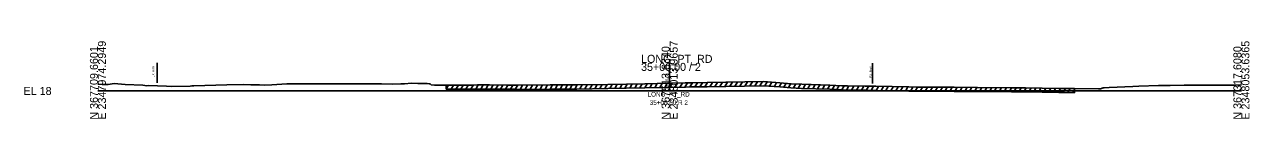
# Model space of a CAD drawing. Extents: x 974 to 2350744, y -10 to 368509.
# Drawn here: x 974.3 to 1402.8, y -9.7 to 17.3 of the extents above; entities that cross this region are included whole.
import ezdxf

# ---------------------------------------------------------------- set-up
doc = ezdxf.new("R2010")
doc.units = 0
for name, color, linetype in [('RD_GPK_XS_Cell', 7, 'Continuous'), ('RD_XS_ExGround', 7, 'Continuous'), ('RD_XS_ExPaveRet', 7, 'Continuous'), ('RD_XS_ExRW', 7, 'Continuous'), ('RD_XS_TX_Elev_EX', 7, 'Continuous'), ('RD_XS_TX_Station', 7, 'Continuous')]:
    doc.layers.add(name, color=color, linetype=linetype)

msp = doc.modelspace()

# ---------------------------------------------------------------- linework, layer by layer
at = {"layer": 'RD_GPK_XS_Cell'}
for p, q in [((1200, 0), (1200, 9.78)), ((1000, 0), (1200, 0)), ((1200, 0), (1400, 0))]:
    msp.add_line(p, q, dxfattribs=at)
at = {"layer": 'RD_XS_ExGround'}
msp.add_lwpolyline([(1000, 2.35), (1001.51, 2.29), (1003.53, 2.22), (1005.71, 2.57), (1009.54, 2.3), (1015.73, 1.98), (1017.13, 1.84), (1017.66, 1.87), (1024.01, 1.67), (1025.56, 1.59), (1032.29, 1.72), (1032.89, 1.78), (1033.59, 1.79), (1045.07, 2.19), (1050.94, 2.23), (1053.49, 2.08), (1056.56, 2.12), (1058.16, 2.01), (1060.88, 2.12), (1066.03, 2.48), (1071.83, 2.44), (1074.52, 2.45), (1079.84, 2.46), (1086.74, 2.43), (1089.22, 2.48), (1097.47, 2.51), (1099.16, 2.47), (1102.87, 2.42), (1105.96, 2.52), (1107.28, 2.5), (1109.68, 2.69), (1111.91, 2.65), (1115.17, 2.61), (1115.88, 2.5), (1116.19, 2.45), (1116.61, 2.09), (1117.72, 2.07), (1118.22, 2.07), (1118.95, 2.06), (1120.46, 2.04), (1121.67, 2.04), (1123.1, 2.04), (1124.36, 2.05), (1125.47, 2.05), (1128.44, 2.05), (1130.03, 2.06), (1131.45, 2.07), (1132.72, 2.08), (1133.84, 2.09), (1134.83, 2.1), (1136.93, 2.1), (1143.65, 2.04), (1145.62, 2.02), (1146.81, 1.99), (1158.24, 2.11), (1167.48, 2.11), (1178.38, 2.28), (1191.31, 2.5), (1200, 2.68), (1205.48, 2.79), (1207.41, 2.82), (1213.13, 2.91), (1232.79, 3.26), (1238.59, 2.81), (1242.49, 2.54), (1246.2, 2.34), (1256.07, 2.04), (1260.2, 1.81), (1262.23, 1.74), (1268.38, 1.68), (1272.18, 1.62), (1283.66, 1.38), (1286.85, 1.33), (1290.04, 1.35), (1299.49, 1.29), (1307.74, 1.26), (1319.56, 1.14), (1324.53, 1.1), (1336.17, 0.88), (1337.71, 0.86), (1341.62, 0.82), (1350.03, 0.76), (1350.76, 0.76), (1351.64, 1.1), (1351.95, 1.12), (1353.69, 1.23), (1362.03, 1.58), (1364.09, 1.65), (1371, 1.91), (1375.1, 1.96), (1380.04, 2), (1386.4, 2.04), (1397.63, 2), (1400, 2.15)], dxfattribs=at)
at = {"layer": 'RD_XS_ExPaveRet'}
for p, q in [((1121.87, 0.63), (1121.87, 2.07)), ((1121.87, 0.6), (1121.87, 2.04)), ((1121.87, 0.75), (1122.61, 2.04)), ((1123.52, 0.6), (1124.35, 2.05)), ((1125.25, 0.61), (1126.08, 2.05)), ((1126.98, 0.61), (1127.81, 2.05)), ((1128.72, 0.61), (1129.55, 2.05)), ((1130.45, 0.62), (1131.29, 2.06)), ((1132.19, 0.64), (1133.03, 2.08)), ((1133.94, 0.65), (1134.77, 2.1)), ((1135.68, 0.67), (1136.51, 2.1)), ((1137.41, 0.66), (1138.23, 2.09)), ((1139.13, 0.65), (1139.95, 2.07)), ((1140.85, 0.63), (1141.67, 2.06)), ((1142.57, 0.61), (1143.4, 2.04)), ((1144.29, 0.59), (1145.12, 2.02)), ((1146.01, 0.57), (1146.83, 1.99)), ((1147.74, 0.56), (1148.57, 2.01)), ((1149.48, 0.58), (1150.32, 2.03)), ((1151.22, 0.6), (1152.06, 2.04)), ((1152.97, 0.62), (1153.8, 2.06)), ((1154.71, 0.63), (1155.54, 2.08)), ((1156.45, 0.65), (1157.29, 2.1)), ((1158.19, 0.67), (1159.02, 2.11)), ((1159.93, 0.67), (1160.76, 2.11)), ((1161.66, 0.67), (1162.49, 2.11)), ((1163.39, 0.67), (1164.22, 2.11)), ((1165.12, 0.67), (1165.95, 2.11)), ((1166.86, 0.67), (1167.69, 2.11)), ((1168.6, 0.69), (1169.44, 2.14)), ((1170.35, 0.72), (1171.18, 2.17)), ((1172.09, 0.74), (1172.93, 2.19)), ((1173.84, 0.77), (1174.68, 2.22)), ((1175.59, 0.8), (1176.43, 2.25)), ((1177.34, 0.82), (1178.17, 2.27)), ((1179.08, 0.85), (1179.92, 2.3)), ((1180.83, 0.88), (1181.67, 2.33)), ((1182.58, 0.91), (1183.42, 2.37)), ((1184.33, 0.94), (1185.17, 2.4)), ((1186.08, 0.98), (1186.92, 2.43)), ((1187.83, 1.01), (1188.67, 2.46)), ((1189.58, 1.04), (1190.42, 2.49)), ((1191.33, 1.07), (1192.17, 2.52)), ((1193.09, 1.1), (1193.93, 2.56)), ((1194.84, 1.14), (1195.68, 2.59)), ((1196.59, 1.17), (1197.43, 2.63)), ((1198.34, 1.21), (1199.18, 2.66)), ((1200.1, 1.24), (1200.93, 2.7)), ((1201.85, 1.28), (1202.69, 2.73)), ((1203.6, 1.31), (1204.44, 2.77)), ((1205.35, 1.35), (1206.19, 2.8)), ((1207.1, 1.38), (1207.94, 2.83)), ((1208.85, 1.41), (1209.69, 2.86)), ((1210.6, 1.43), (1211.43, 2.88)), ((1212.34, 1.46), (1213.18, 2.91)), ((1214.09, 1.49), (1214.93, 2.94)), ((1215.84, 1.52), (1216.68, 2.97)), ((1217.59, 1.55), (1218.43, 3.01)), ((1219.34, 1.58), (1220.18, 3.04)), ((1221.09, 1.62), (1221.93, 3.07)), ((1222.84, 1.65), (1223.68, 3.1)), ((1224.59, 1.68), (1225.43, 3.13)), ((1226.34, 1.71), (1227.18, 3.16)), ((1228.09, 1.74), (1228.93, 3.19)), ((1229.84, 1.77), (1230.68, 3.22)), ((1231.59, 1.8), (1232.43, 3.25)), ((1233.31, 1.78), (1234.11, 3.16)), ((1234.97, 1.65), (1235.77, 3.03)), ((1236.63, 1.52), (1237.42, 2.9)), ((1238.29, 1.39), (1239.08, 2.78)), ((1239.95, 1.28), (1240.75, 2.66)), ((1241.62, 1.16), (1242.42, 2.55)), ((1243.29, 1.06), (1244.1, 2.46)), ((1244.97, 0.97), (1245.78, 2.37)), ((1246.66, 0.89), (1247.47, 2.31)), ((1248.36, 0.84), (1249.17, 2.25)), ((1250.06, 0.79), (1250.88, 2.2)), ((1251.76, 0.74), (1252.58, 2.15)), ((1253.46, 0.68), (1254.28, 2.1)), ((1255.17, 0.63), (1255.98, 2.04)), ((1256.86, 0.56), (1257.66, 1.95)), ((1258.53, 0.46), (1259.34, 1.85)), ((1260.21, 0.37), (1261.03, 1.78)), ((1261.91, 0.31), (1262.73, 1.73)), ((1263.63, 0.29), (1264.45, 1.72)), ((1265.35, 0.27), (1266.18, 1.7)), ((1267.07, 0.25), (1267.9, 1.68)), ((1268.79, 0.23), (1269.62, 1.66)), ((1270.51, 0.21), (1271.33, 1.63)), ((1272.23, 0.18), (1273.05, 1.6)), ((1273.94, 0.14), (1274.76, 1.56)), ((1275.65, 0.11), (1276.47, 1.53)), ((1277.36, 0.07), (1278.18, 1.49)), ((1279.07, 0.04), (1279.89, 1.46)), ((1280.79, 0), (1281.61, 1.43)), ((1282.5, -0.03), (1283.32, 1.39)), ((1284.21, -0.06), (1285.03, 1.36)), ((1285.93, -0.09), (1286.75, 1.33)), ((1287.65, -0.1), (1288.48, 1.34)), ((1289.39, -0.1), (1290.22, 1.34)), ((1291.12, -0.1), (1291.95, 1.33)), ((1292.85, -0.11), (1293.67, 1.33)), ((1294.57, -0.12), (1295.4, 1.32)), ((1296.3, -0.13), (1297.13, 1.31)), ((1298.03, -0.14), (1298.85, 1.3)), ((1299.75, -0.15), (1300.58, 1.29)), ((1301.48, -0.15), (1302.31, 1.28)), ((1303.21, -0.16), (1304.04, 1.27)), ((1304.94, -0.17), (1305.76, 1.27)), ((1306.66, -0.17), (1307.49, 1.26)), ((1308.39, -0.18), (1309.21, 1.24)), ((1310.11, -0.2), (1310.94, 1.23)), ((1311.83, -0.22), (1312.66, 1.21)), ((1313.56, -0.23), (1314.38, 1.19)), ((1315.28, -0.25), (1316.1, 1.18)), ((1317, -0.27), (1317.83, 1.16)), ((1318.72, -0.28), (1319.55, 1.14)), ((1320.45, -0.3), (1321.27, 1.13)), ((1322.17, -0.32), (1323, 1.11)), ((1323.89, -0.33), (1324.72, 1.1)), ((1325.61, -0.36), (1326.43, 1.07)), ((1327.32, -0.39), (1328.15, 1.03)), ((1329.04, -0.42), (1329.86, 1)), ((1330.75, -0.45), (1331.57, 0.97)), ((1332.46, -0.49), (1333.29, 0.94)), ((1334.18, -0.52), (1335, 0.9)), ((1335.89, -0.55), (1336.71, 0.87)), ((1337.61, -0.58), (1338.43, 0.85)), ((1339.33, -0.6), (1340.15, 0.83)), ((1341.05, -0.61), (1341.62, 0.37)), ((1341.62, -0.62), (1341.62, 0.82))]:
    msp.add_line(p, q, dxfattribs=at)
msp.add_lwpolyline([(1121.87, 0.6), (1123.1, 0.6), (1124.37, 0.61), (1125.47, 0.62), (1128.44, 0.61), (1130.04, 0.62), (1131.47, 0.63), (1132.73, 0.64), (1133.85, 0.65), (1134.84, 0.67), (1136.92, 0.67), (1143.64, 0.6), (1145.59, 0.58), (1146.8, 0.55), (1158.25, 0.67), (1167.49, 0.67), (1178.4, 0.84), (1191.33, 1.07), (1200.03, 1.24), (1205.51, 1.35), (1207.44, 1.38), (1213.16, 1.47), (1232.75, 1.82), (1238.49, 1.38), (1242.4, 1.11), (1246.14, 0.91), (1256.01, 0.61), (1260.13, 0.37), (1262.2, 0.3), (1268.36, 0.24), (1272.16, 0.18), (1283.63, -0.05), (1286.84, -0.11), (1290.04, -0.09), (1299.48, -0.14), (1307.73, -0.18), (1319.55, -0.29), (1324.51, -0.34), (1336.15, -0.55), (1337.69, -0.58), (1341.62, -0.62)], dxfattribs=at)
at = {"layer": 'RD_XS_ExRW'}
for p, q in [((1020.76, 2.78), (1020.76, 9.78)), ((1271, 2.64), (1271, 9.64))]:
    msp.add_line(p, q, dxfattribs=at)

# ---------------------------------------------------------------- texts
at = {"layer": 'RD_GPK_XS_Cell'}
for s, p in [('E 2347974.2949', (1002.8, -10)), ('E 2348013.9657', (1202.8, -10)), ('E 2348053.6365', (1402.8, -10)), ('N 367709.6601', (1000, -10)), ('N 367513.6340', (1200, -10)), ('N 367317.6080', (1400, -10))]:
    msp.add_text(s, height=2.8, rotation=90, dxfattribs=at).set_placement(p)
for s, p in [('35+00.00 / 2', (1190, 6.98)), ('LONG_PT_RD', (1190, 9.78)), ('EL 18', (974, -1.4))]:
    msp.add_text(s, height=2.8, dxfattribs=at).set_placement(p)
at = {"layer": 'RD_XS_ExRW'}
for p in [(1019.75, 4.73), (1270.75, 4.59)]:
    msp.add_text('EX. R/W ', height=0.75, rotation=90, dxfattribs=at).set_placement(p)
at = {"layer": 'RD_XS_TX_Elev_EX'}
msp.add_text('20.68', height=1, rotation=90, dxfattribs=at).set_placement((1199.51, 2.68))
at = {"layer": 'RD_XS_TX_Station'}
for s, p in [('LONG_PT_RD', (1192.28, -1.96)), ('35+00.00 R 2', (1193.04, -4.86))]:
    msp.add_text(s, height=1.6, dxfattribs=at).set_placement(p)

doc.saveas('drawing.dxf')
